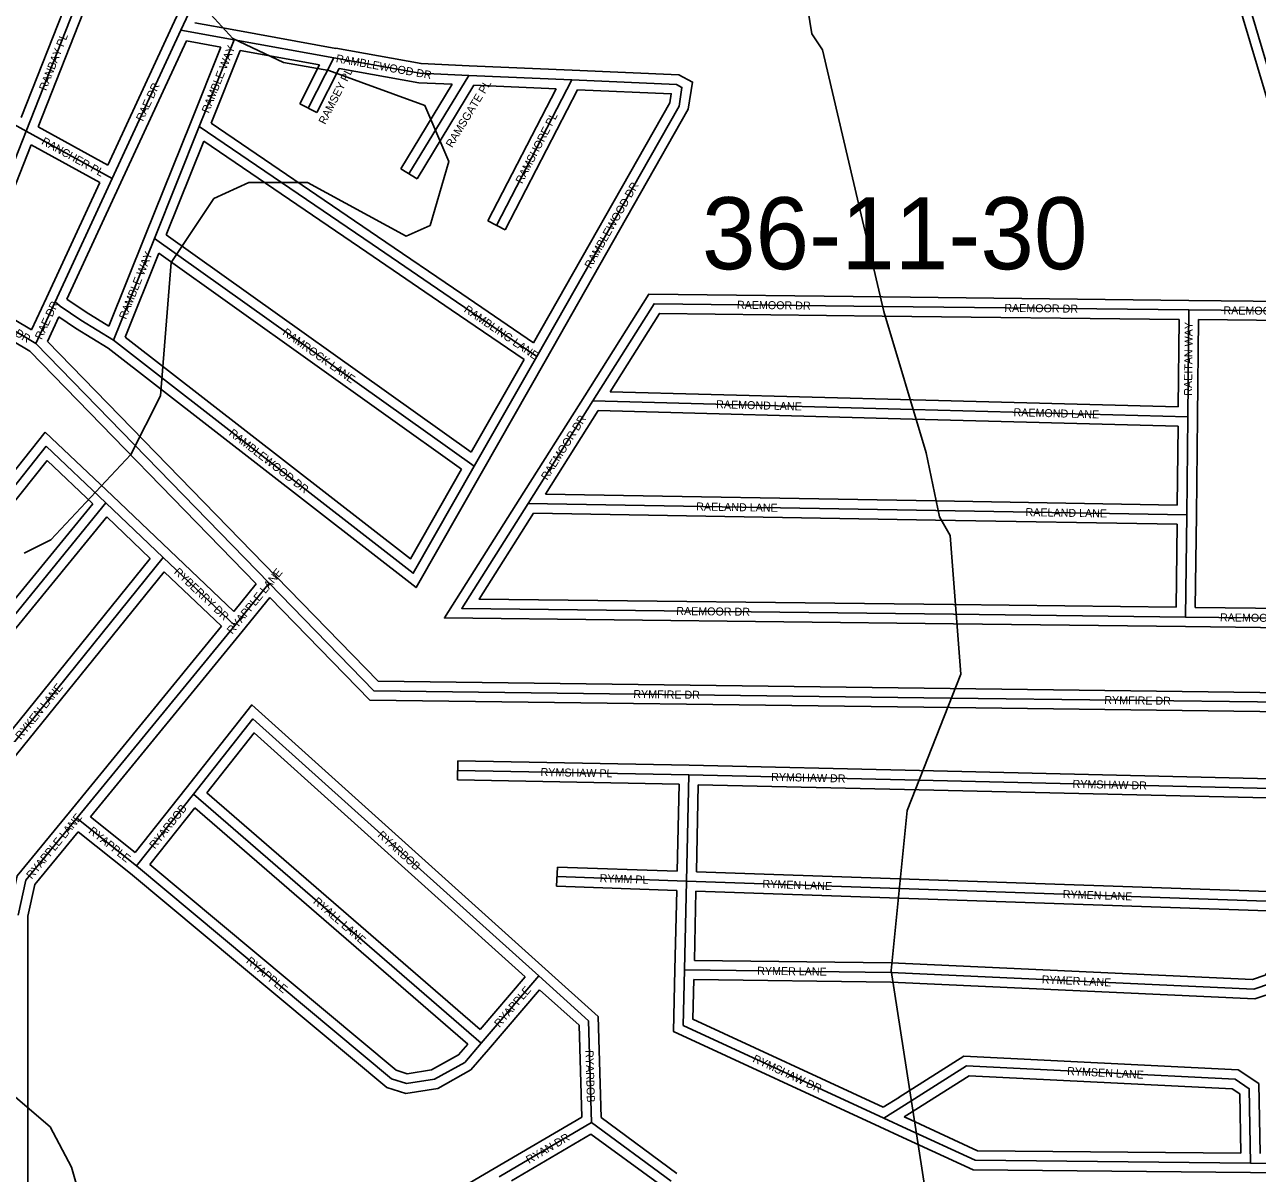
# Model space of a CAD drawing. Extents: x 457167 to 656239, y 1787309 to 1969297.
# Drawn here: x 580690 to 584541, y 1878702 to 1882291 of the extents above; entities that cross this region are included whole.
import ezdxf

# ---------------------------------------------------------------- set-up
doc = ezdxf.new("R2010")
doc.units = 0
for name, color, linetype in [('Level 2', 7, 'Continuous'), ('Level 31', 7, 'Continuous'), ('Level 32', 7, 'Continuous'), ('Level 34', 7, 'Continuous'), ('Level 5', 7, 'Continuous'), ('Level 7', 7, 'Continuous')]:
    doc.layers.add(name, color=color, linetype=linetype)

msp = doc.modelspace()

# ---------------------------------------------------------------- linework, layer by layer
at = {"layer": 'Level 31'}
for p, q in [((581178.683, 1882274.11), (581288.904, 1882512.797)), ((580859.526, 1882376.576), (580695.181, 1881958.726)), ((580963.989, 1881810.541), (581178.683, 1882274.11)), ((581178.683, 1882274.11), (581344.347, 1882243.956)), ((581235.967, 1881972.537), (581344.347, 1882243.956)), ((581344.347, 1882243.956), (581656.599, 1882187.691)), ((581656.599, 1882187.691), (581576.125, 1882030.397)), ((582077.324, 1882132.665), (581890.627, 1881825.037)), ((582077.324, 1882132.665), (582399.206, 1882118.568)), ((580695.181, 1881958.726), (580451.478, 1882093.405)), ((582399.206, 1882118.568), (582164.186, 1881664.126)), ((580695.181, 1881958.726), (580537.229, 1881558.317)), ((580963.989, 1881810.541), (580695.181, 1881958.726)), ((581095.939, 1881623.364), (581235.967, 1881972.537)), ((581235.967, 1881972.537), (581775.673, 1881604.902)), ((580785.711, 1881425.447), (580963.989, 1881810.541)), ((580968.056, 1881305.076), (581095.939, 1881623.364)), ((581095.939, 1881623.364), (582094.616, 1880911.532)), ((581775.673, 1881604.902), (582039.335, 1881425.101)), ((580482.91, 1881439.156), (580725.326, 1881295.024)), ((580725.326, 1881295.024), (580785.711, 1881425.447)), ((582039.335, 1881425.101), (582289.975, 1881254.416)), ((584327.046, 1881399.867), (583369.592, 1881410.827)), ((584327.046, 1881399.867), (584323.539, 1881066.056)), ((584738.338, 1881395.436), (584327.046, 1881399.867)), ((580725.326, 1881295.024), (581454.179, 1880546.271)), ((582289.975, 1881254.416), (582094.616, 1880911.532)), ((582465.609, 1881115.886), (582262.979, 1880795.196)), ((582465.609, 1881115.886), (583464.711, 1881088.821)), ((583464.711, 1881088.821), (584323.539, 1881066.056)), ((584323.539, 1881066.056), (584320.403, 1880759.878)), ((580615.84, 1880795.244), (580757.758, 1880973.866)), ((580757.758, 1880973.866), (580943.809, 1880797.122)), ((580147.513, 1879822.378), (580943.809, 1880797.122)), ((580943.809, 1880797.122), (581123.192, 1880626.212)), ((582262.979, 1880795.196), (583536.304, 1880773.042)), ((583536.304, 1880773.042), (584320.403, 1880759.878)), ((584320.403, 1880759.878), (584316.605, 1880440.611)), ((580332.616, 1879647.816), (581123.192, 1880626.212)), ((581123.192, 1880626.212), (581346.394, 1880414.123)), ((581346.394, 1880414.123), (581454.179, 1880546.271)), ((583591.658, 1880449.296), (584316.605, 1880440.611)), ((584316.605, 1880440.611), (584727.272, 1880436.181)), ((580853.382, 1879811.846), (581346.394, 1880414.123)), ((583581.286, 1880187.496), (584723.904, 1880172.913)), ((582765.183, 1879947.284), (582042.781, 1879961.449)), ((582757.848, 1879615.297), (582765.183, 1879947.284)), ((582765.183, 1879947.284), (583485.034, 1879930.593)), ((583485.034, 1879930.593), (584648.313, 1879903.603)), ((581218.089, 1879887.107), (581040.13, 1879662.739)), ((581218.089, 1879887.107), (582116.797, 1879109.297)), ((581040.13, 1879662.739), (580853.382, 1879811.846)), ((582757.848, 1879615.297), (582353.235, 1879629.556)), ((582751.575, 1879338.218), (582757.848, 1879615.297)), ((583423.296, 1879592.531), (582757.848, 1879615.297)), ((584633.957, 1879550.901), (583423.296, 1879592.531)), ((582116.797, 1879109.297), (582295.995, 1879319.122)), ((583396.38, 1879330.036), (582751.575, 1879338.218)), ((583374.176, 1878874.806), (583438.514, 1878915.044)), ((582172.273, 1878691.366), (582461.144, 1878860.974)), ((582461.144, 1878860.974), (582710.191, 1878678.296)), ((583445.689, 1878841.938), (583374.176, 1878874.806)), ((584966.408, 1878730.623), (584519.774, 1878734.756))]:
    msp.add_line(p, q, dxfattribs=at)
for points in [[(584738.338, 1881395.436), (584740.629, 1881595.434), (584504.858, 1882388.62)], [(581656.599, 1882187.691), (581925.29, 1882139.515), (582077.324, 1882132.665)], [(582399.206, 1882118.568), (582726.177, 1882104.464), (582743.654, 1882095.339), (582734.631, 1882036.811), (582289.975, 1881254.416)], [(580968.056, 1881305.076), (580865.756, 1881367.83), (580801.589, 1881411.596), (580785.711, 1881425.447)], [(583369.592, 1881410.827), (582656.751, 1881419.143), (582465.609, 1881115.886)], [(582094.616, 1880911.532), (581904.36, 1880577.366), (580968.056, 1881305.076)], [(582262.979, 1880795.196), (582055.559, 1880467.245), (583591.658, 1880449.296)], [(581454.179, 1880546.271), (581781.474, 1880210.338), (583581.286, 1880187.496)], [(582295.995, 1879319.122), (581403.384, 1880122.007), (581218.089, 1879887.107)], [(580670.49, 1879509.308), (580694.569, 1879617.986), (580853.382, 1879811.846)], [(581040.13, 1879662.739), (581836.312, 1878997.858), (581883.046, 1878982.856), (581970.875, 1878996.861), (582064.824, 1879049.037), (582116.797, 1879109.297)], [(584633.957, 1879550.901), (584626.96, 1879386.551), (584611.902, 1879330.944), (584582.249, 1879295.728), (584529.409, 1879278.376), (583396.38, 1879330.036)], [(582461.144, 1878860.974), (582451.913, 1879178.811), (582295.995, 1879319.122)], [(583374.176, 1878874.806), (582747.415, 1879164.771), (582751.575, 1879338.218)], [(583438.514, 1878915.044), (583632.489, 1879037.936), (584471.605, 1878996.304), (584515.448, 1878966.765), (584519.774, 1878734.756)], [(584519.774, 1878734.756), (583659.592, 1878743.337), (583445.689, 1878841.938)]]:
    msp.add_lwpolyline(points, dxfattribs=at)
at = {"layer": 'Level 32'}
for p, q in [((581151.446, 1882286.687), (581261.668, 1882525.375)), ((580831.609, 1882387.556), (580679.774, 1882001.516)), ((580887.445, 1882365.594), (580732.749, 1881972.273)), ((580950.29, 1881852.349), (581151.46, 1882286.717)), ((581222.156, 1882296.69), (581349.719, 1882273.472)), ((581349.667, 1882273.481), (581661.92, 1882217.216)), ((580991.212, 1881797.933), (581196.149, 1882240.436)), ((581196.15, 1882240.436), (581302.882, 1882221.009)), ((581208.107, 1881983.662), (581302.882, 1882221.009)), ((581272.759, 1881983.774), (581363.128, 1882210.087)), ((581363.128, 1882210.087), (581611.466, 1882165.339)), ((581611.467, 1882165.339), (581549.419, 1882044.061)), ((581673.184, 1882154.237), (581602.834, 1882016.731)), ((582078.638, 1882162.636), (582400.519, 1882148.54)), ((582025.426, 1882104.971), (581864.98, 1881840.602)), ((582093.757, 1882101.915), (581916.274, 1881809.471)), ((582093.757, 1882101.915), (582350.994, 1882090.649)), ((582350.994, 1882090.649), (582137.539, 1881677.906)), ((582417.054, 1882087.769), (582190.834, 1881650.343)), ((581602.834, 1882016.731), (581549.419, 1882044.061)), ((581068.094, 1881634.531), (581208.123, 1881983.704)), ((581272.759, 1881983.775), (581792.563, 1881629.697)), ((580950.29, 1881852.349), (580732.749, 1881972.273)), ((580710.572, 1881915.984), (580565.137, 1881547.307)), ((580925.018, 1881797.769), (580710.572, 1881915.984)), ((581132.567, 1881634.096), (581249.922, 1881926.732)), ((581249.922, 1881926.731), (581758.784, 1881580.107)), ((581916.274, 1881809.471), (581864.98, 1881840.602)), ((580758.488, 1881438.051), (580925.018, 1881797.768)), ((580822.552, 1881433.613), (580991.214, 1881797.937)), ((582190.834, 1881650.343), (582137.539, 1881677.906)), ((580953.463, 1881349.222), (581068.101, 1881634.548)), ((581132.567, 1881634.097), (582084.989, 1880955.236)), ((581792.575, 1881629.688), (582056.238, 1881449.886)), ((581004.329, 1881314.881), (581109.566, 1881576.809)), ((581109.566, 1881576.808), (582055.14, 1880902.829)), ((581758.772, 1881580.116), (582022.434, 1881400.314)), ((580498.243, 1881464.941), (580712.076, 1881337.805)), ((580712.075, 1881337.805), (580758.488, 1881438.051)), ((582056.222, 1881449.897), (582279.969, 1881297.526)), ((584327.389, 1881429.866), (583369.935, 1881440.826)), ((580467.579, 1881413.368), (580706.592, 1881271.26)), ((582022.449, 1881400.303), (582250.2, 1881245.206)), ((584708.684, 1881425.756), (584327.369, 1881429.866)), ((580761.226, 1881301.154), (580796.996, 1881378.414)), ((584296.733, 1881370.211), (583369.249, 1881380.828)), ((584296.733, 1881370.211), (584293.86, 1881096.852)), ((584356.731, 1881369.545), (584353.538, 1881065.74)), ((584708.008, 1881365.761), (584356.731, 1881369.545)), ((580761.226, 1881301.154), (581475.676, 1880567.196)), ((580706.593, 1881271.26), (581414.028, 1880544.507)), ((582250.2, 1881245.206), (582084.989, 1880955.236)), ((582316.043, 1881239.565), (582120.684, 1880896.681)), ((582440.248, 1881131.911), (582237.618, 1880811.221)), ((582519.077, 1881144.448), (583465.524, 1881118.81)), ((583465.506, 1881118.811), (584293.861, 1881096.852)), ((582481.857, 1881085.432), (582316.834, 1880824.263)), ((582481.856, 1881085.433), (583463.899, 1881058.831)), ((583463.916, 1881058.83), (584293.238, 1881036.846)), ((584353.538, 1881065.747), (584350.402, 1880759.57)), ((580592.351, 1880813.906), (580754.658, 1881018.19)), ((580754.658, 1881018.19), (580964.471, 1880818.873)), ((584293.238, 1881036.847), (584290.714, 1880790.381)), ((580639.329, 1880776.58), (580760.859, 1880929.539)), ((580760.859, 1880929.539), (580902.965, 1880794.543)), ((582316.834, 1880824.263), (583536.826, 1880803.038)), ((580144.677, 1879866.326), (580902.965, 1880794.543)), ((580964.503, 1880818.842), (581143.886, 1880647.932)), ((583536.808, 1880803.038), (584290.714, 1880790.38)), ((580188.424, 1879825.034), (580946.559, 1880753.066)), ((580946.559, 1880753.066), (581082.482, 1880623.563)), ((582279.32, 1880764.905), (583535.783, 1880743.046)), ((583535.801, 1880743.046), (584290.05, 1880730.382)), ((584350.401, 1880759.521), (584346.962, 1880470.285)), ((584290.05, 1880730.381), (584286.964, 1880470.968)), ((581143.857, 1880647.961), (581343.599, 1880458.161)), ((580329.638, 1879691.862), (581082.482, 1880623.563)), ((580373.424, 1879650.583), (581126.095, 1880582.069)), ((581126.095, 1880582.069), (581305.533, 1880411.566)), ((581343.6, 1880458.161), (581414.028, 1880544.507)), ((581369.642, 1880395.161), (581456.166, 1880501.24)), ((583592.018, 1880479.294), (584286.964, 1880470.968)), ((584346.962, 1880470.285), (584697.647, 1880466.501)), ((580830.169, 1879830.849), (581305.533, 1880411.566)), ((583591.299, 1880419.296), (584316.246, 1880410.611)), ((584316.282, 1880410.611), (584696.89, 1880406.506)), ((580895.834, 1879816.341), (581369.609, 1880395.12)), ((583581.669, 1880217.495), (584694.29, 1880203.294)), ((583580.904, 1880157.498), (584723.522, 1880142.914)), ((582042.194, 1879931.453), (582043.369, 1879991.444)), ((582765.771, 1879977.279), (582043.369, 1879991.444)), ((582765.879, 1879977.276), (583485.729, 1879960.586)), ((583485.73, 1879960.586), (584649.009, 1879933.596)), ((581194.586, 1879905.75), (581035.329, 1879704.962)), ((582734.527, 1879917.877), (582042.194, 1879931.453)), ((582728.527, 1879646.348), (582734.526, 1879917.877)), ((582788.497, 1879644.266), (582794.514, 1879916.595)), ((582794.514, 1879916.595), (583484.339, 1879900.601)), ((583484.339, 1879900.601), (584617.096, 1879874.317)), ((581259.399, 1879891.031), (582113.597, 1879151.743)), ((581222.135, 1879843.93), (581081.814, 1879667.015)), ((581222.135, 1879843.93), (582074.519, 1879106.212)), ((581035.329, 1879704.962), (580895.834, 1879816.341)), ((581021.154, 1879639.5), (580857.816, 1879769.916)), ((582352.179, 1879599.573), (582354.293, 1879659.536)), ((582728.527, 1879646.348), (582354.293, 1879659.536)), ((583424.323, 1879622.513), (582788.497, 1879644.266)), ((582727.185, 1879586.358), (582352.179, 1879599.573)), ((584605.194, 1879581.908), (583424.328, 1879622.513)), ((582721.583, 1879338.896), (582727.185, 1879586.358)), ((582782.254, 1879367.831), (582787.154, 1879584.275)), ((583422.271, 1879562.547), (582787.154, 1879584.276)), ((584602.698, 1879521.957), (583422.266, 1879562.547)), ((580700.287, 1878938.384), (580700.49, 1879506.018)), ((583397.254, 1879360.028), (582782.254, 1879367.831)), ((582113.597, 1879151.743), (582254.194, 1879316.371)), ((583395.508, 1879300.043), (582780.857, 1879307.842)), ((582139.61, 1879089.814), (582298.814, 1879276.226)), ((580699.886, 1878444.928), (580700.287, 1878938.371)), ((583372.036, 1878908.851), (583422.608, 1878940.479)), ((582157.083, 1878717.237), (582430.642, 1878877.852)), ((582490.708, 1878876.496), (582727.935, 1878702.487)), ((583437.22, 1878878.848), (583454.423, 1878889.607)), ((583458.217, 1878869.197), (583437.22, 1878878.848)), ((582210.764, 1878679.176), (582459.316, 1878825.11)), ((582459.316, 1878825.109), (582670.29, 1878670.357)), ((583433.162, 1878814.679), (583361.649, 1878847.546)), ((584935.64, 1878700.905), (584519.496, 1878704.756))]:
    msp.add_line(p, q, dxfattribs=at)
for points in [[(584708.684, 1881425.757), (584710.579, 1881591.237), (584476.1, 1882380.072)], [(581661.894, 1882217.221), (581928.628, 1882169.396), (582078.675, 1882162.636)], [(581673.184, 1882154.237), (581921.954, 1882109.634), (582025.426, 1882104.971)], [(582400.499, 1882148.541), (582734.141, 1882134.149), (582776.576, 1882111.992), (582763.441, 1882026.785), (582316.058, 1881239.593)], [(582417.054, 1882087.769), (582710.183, 1882075.126), (582705.821, 1882046.836), (582279.969, 1881297.527)], [(583369.941, 1881440.826), (582640.319, 1881449.338), (582440.229, 1881131.882)], [(580953.463, 1881349.223), (580882.061, 1881393.023), (580822.552, 1881433.613)], [(580950.958, 1881280.37), (580849.451, 1881342.636), (580796.996, 1881378.414)], [(583369.242, 1881380.828), (582673.182, 1881388.949), (582519.076, 1881144.448)], [(582055.14, 1880902.829), (581895.424, 1880622.307), (581004.329, 1881314.881)], [(582120.688, 1880896.689), (581913.296, 1880532.425), (580950.957, 1881280.37)], [(582237.624, 1880811.232), (582001.485, 1880437.874), (583591.308, 1880419.296)], [(582279.32, 1880764.905), (582109.633, 1880496.616), (583592.009, 1880479.295)], [(581475.666, 1880567.206), (581794.286, 1880240.179), (583581.667, 1880217.495)], [(581456.166, 1880501.24), (581768.663, 1880180.497), (583580.906, 1880157.499)], [(582316.058, 1879341.427), (581399.652, 1880165.716), (581194.536, 1879905.687)], [(582254.194, 1879316.371), (581407.117, 1880078.299), (581259.398, 1879891.031)], [(580646.761, 1879540.891), (580666.827, 1879631.463), (580830.175, 1879830.858)], [(580700.491, 1879506.018), (580722.311, 1879604.51), (580857.815, 1879769.915)], [(581081.815, 1879667.016), (581851.051, 1879024.635), (581885.395, 1879013.61), (581960.93, 1879025.656), (582045.592, 1879072.673), (582074.52, 1879106.211)], [(581021.154, 1879639.5), (581821.574, 1878971.081), (581880.698, 1878952.101), (581980.819, 1878968.067), (582084.056, 1879025.401), (582139.515, 1879089.703)], [(584663.929, 1879549.626), (584656.792, 1879381.936), (584639.125, 1879316.696), (584599.708, 1879269.884), (584533.54, 1879248.156), (583395.508, 1879300.044)], [(584602.698, 1879521.957), (584597.129, 1879391.167), (584584.679, 1879345.191), (584564.791, 1879321.571), (584525.278, 1879308.596), (583397.254, 1879360.027)], [(582490.708, 1878876.495), (582481.528, 1879192.521), (582316.063, 1879341.423)], [(583361.579, 1878847.577), (582716.952, 1879145.809), (582721.583, 1879338.937)], [(583372.035, 1878908.851), (582777.879, 1879183.731), (582780.857, 1879307.842)], [(582430.643, 1878877.853), (582422.298, 1879165.103), (582298.814, 1879276.226)], [(583422.459, 1878940.386), (583624.472, 1879068.372), (584481.439, 1879025.854), (584545.152, 1878982.926), (584549.225, 1878764.484)], [(583454.57, 1878889.701), (583640.506, 1879007.501), (584461.772, 1878966.754), (584485.744, 1878950.603), (584489.204, 1878765.062)], [(584489.204, 1878765.062), (583666.316, 1878773.272), (583458.248, 1878869.184)], [(584519.474, 1878704.756), (583652.868, 1878713.402), (583433.13, 1878814.693)], [(580965.491, 1878449.606), (581724.037, 1878463.552), (582157.108, 1878717.253)]]:
    msp.add_lwpolyline(points, dxfattribs=at)
at = {"layer": 'Level 5'}
msp.add_lwpolyline([(583562.149, 1878269.148), (583396.553, 1879336.403), (583447.127, 1879836.515), (583614.304, 1880261.506), (583581.417, 1880695.026), (583548.136, 1880753.418), (583506.643, 1880953.552), (583373.754, 1881395.512), (583182.861, 1882212.671), (583149.579, 1882262.722), (583116.457, 1882462.827), (583049.864, 1882554.629)], dxfattribs=at)
at = {"layer": 'Level 7'}
for points in [[(580688.656, 1880639.781), (580772.057, 1880681.361), (581022.437, 1880947.86), (581114.326, 1881131.165), (581148.131, 1881547.955), (581281.7, 1881747.861), (581390.141, 1881797.782), (581573.534, 1881797.583), (581881.78, 1881630.531), (581956.841, 1881663.781), (582015.419, 1881863.786), (581940.595, 1882038.951), (581640.579, 1882147.651), (581498.898, 1882172.791), (581340.574, 1882248.012), (581249.002, 1882348.145)], [(580394.719, 1878597.659), (580777.928, 1878347.186), (580886.497, 1878547.121), (580836.674, 1878722.255), (580770.111, 1878847.357), (580370.321, 1879189.573)]]:
    msp.add_lwpolyline(points, dxfattribs=at)

# ---------------------------------------------------------------- texts
at = {"layer": 'Level 2'}
msp.add_text('36-11-30', height=225, dxfattribs=at).set_placement((582806.006, 1881527.056))
at = {"layer": 'Level 34'}
for s, height, rotation, p in [('RANBAY PL', 25, 68.528758, (580757.513, 1882083.058)), ('RAMBLE WAY', 25, 68.231953, (581265.499, 1882012.789)), ('RAMBLEWOOD DR', 25, 349.83475, (581661.322, 1882174.146)), ('RAMSEY PL', 25, 62.903969, (581629.137, 1881977.419)), ('RAE DR', 25, 65.148656, (581059.646, 1881987.344)), ('RAMSGATE PL', 25, 58.745781, (582025.397, 1881904.953)), ('RAMSHORE PL', 25, 62.65295, (582244.402, 1881792.024)), ('RANCHER PL', 25, 331.1335, (580740.803, 1881919.303)), ('RAMBLEWOOD DR', 25, 60.388317, (582459.207, 1881526.896)), ('RAMBLE WAY', 25, 68.109836, (581007.135, 1881368.816)), ('RYMFIRE DR', 25, 329.26575, (580520.574, 1881402.219)), ('RAE DR', 25, 65.15535, (580743.836, 1881305.252)), ('RAMBLING LANE', 25, 325.745408, (582060.385, 1881395.642)), ('RAEMOOR DR', 25, 359.331317, (582915.238, 1881403.628)), ('RAEMOOR DR', 25, 359.343922, (583750.387, 1881393.969)), ('RAEMOOR DR', 25, 359.382422, (584434.767, 1881386.206)), ('RAEITAN WAY', 25, 89.397275, (584336.728, 1881131.732)), ('RAMROCK LANE', 25, 324.519528, (581493.766, 1881324.453)), ('RAEMOND LANE', 25, 358.448031, (582850.061, 1881092.966)), ('RAEMOND LANE', 24.99916, 358.481286, (583779.035, 1881067.985)), ('RAEMOOR DR', 25, 57.711956, (582322.622, 1880866.189)), ('RAMBLEWOOD DR', 25, 322.144883, (581326.329, 1881010.79)), ('RAELAND LANE', 25, 359.002972, (582787.944, 1880773.561)), ('RAELAND LANE', 25, 359.037839, (583816.663, 1880755.834)), ('RYBERRY DR', 25, 316.462156, (581154.947, 1880578.796)), ('RYAPPLE LANE', 25, 50.796817, (581338.902, 1880385.164)), ('RAEMOOR DR', 25, 359.330264, (582725.674, 1880446.915)), ('RAEMOOR DR', 25, 359.381647, (584424.014, 1880426.952)), ('RYKEN LANE', 25, 51.059811, (580678.24, 1880055.665)), ('RYMFIRE DR', 25, 359.272622, (582591.466, 1880187.558)), ('RYMFIRE DR', 25, 359.268469, (584062.679, 1880168.851)), ('RYMSHAW PL', 25, 358.8764, (582301.71, 1879943.87)), ('RYMSHAW DR', 25, 358.671433, (583021.854, 1879928.83)), ('RYMSHAW DR', 25, 358.670597, (583963.419, 1879906.991)), ('RYAPPLE LANE', 24.99916, 50.6743, (580712.391, 1879620.019)), ('RYARBOB', 25, 51.579239, (581096.92, 1879714.225)), ('RYAPPLE', 25, 321.394664, (580888.008, 1879768.204)), ('RYARBOB', 25, 318.029086, (581791.101, 1879756.451)), ('RYMM PL', 25, 357.981517, (582486.168, 1879612.364)), ('RYMEN LANE', 25, 358.040272, (582994.767, 1879594.685)), ('RYMEN LANE', 25, 358.030369, (583932.819, 1879562.504)), ('RYALL LANE', 25, 319.124364, (581589.96, 1879548.731)), ('RYAPPLE', 25, 320.134978, (581380.167, 1879362.494)), ('RYMER LANE', 25, 359.27285, (582978.393, 1879322.84)), ('RYMER LANE', 25, 357.389081, (583866.991, 1879296.066)), ('RYAPPLE', 25, 49.500592, (582173.559, 1879156.516)), ('RYARBOB', 25, 271.663069, (582442.073, 1879087.061)), ('RYMSHAW DR', 25, 335.172675, (582962.074, 1879051.688)), ('RYMSEN LANE', 25, 357.15935, (583946.203, 1879009.857)), ('RYAN DR', 25, 30.418069, (582265.593, 1878731.664))]:
    msp.add_text(s, height=height, rotation=rotation, dxfattribs=at).set_placement(p)

doc.saveas('drawing.dxf')
